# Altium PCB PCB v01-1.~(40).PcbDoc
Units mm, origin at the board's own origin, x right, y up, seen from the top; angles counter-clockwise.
Board outline 65 x 71 mm, 2 copper layers (Top Layer, Bottom Layer); 80 components, 36 nets, 162 pads, 11 vias.
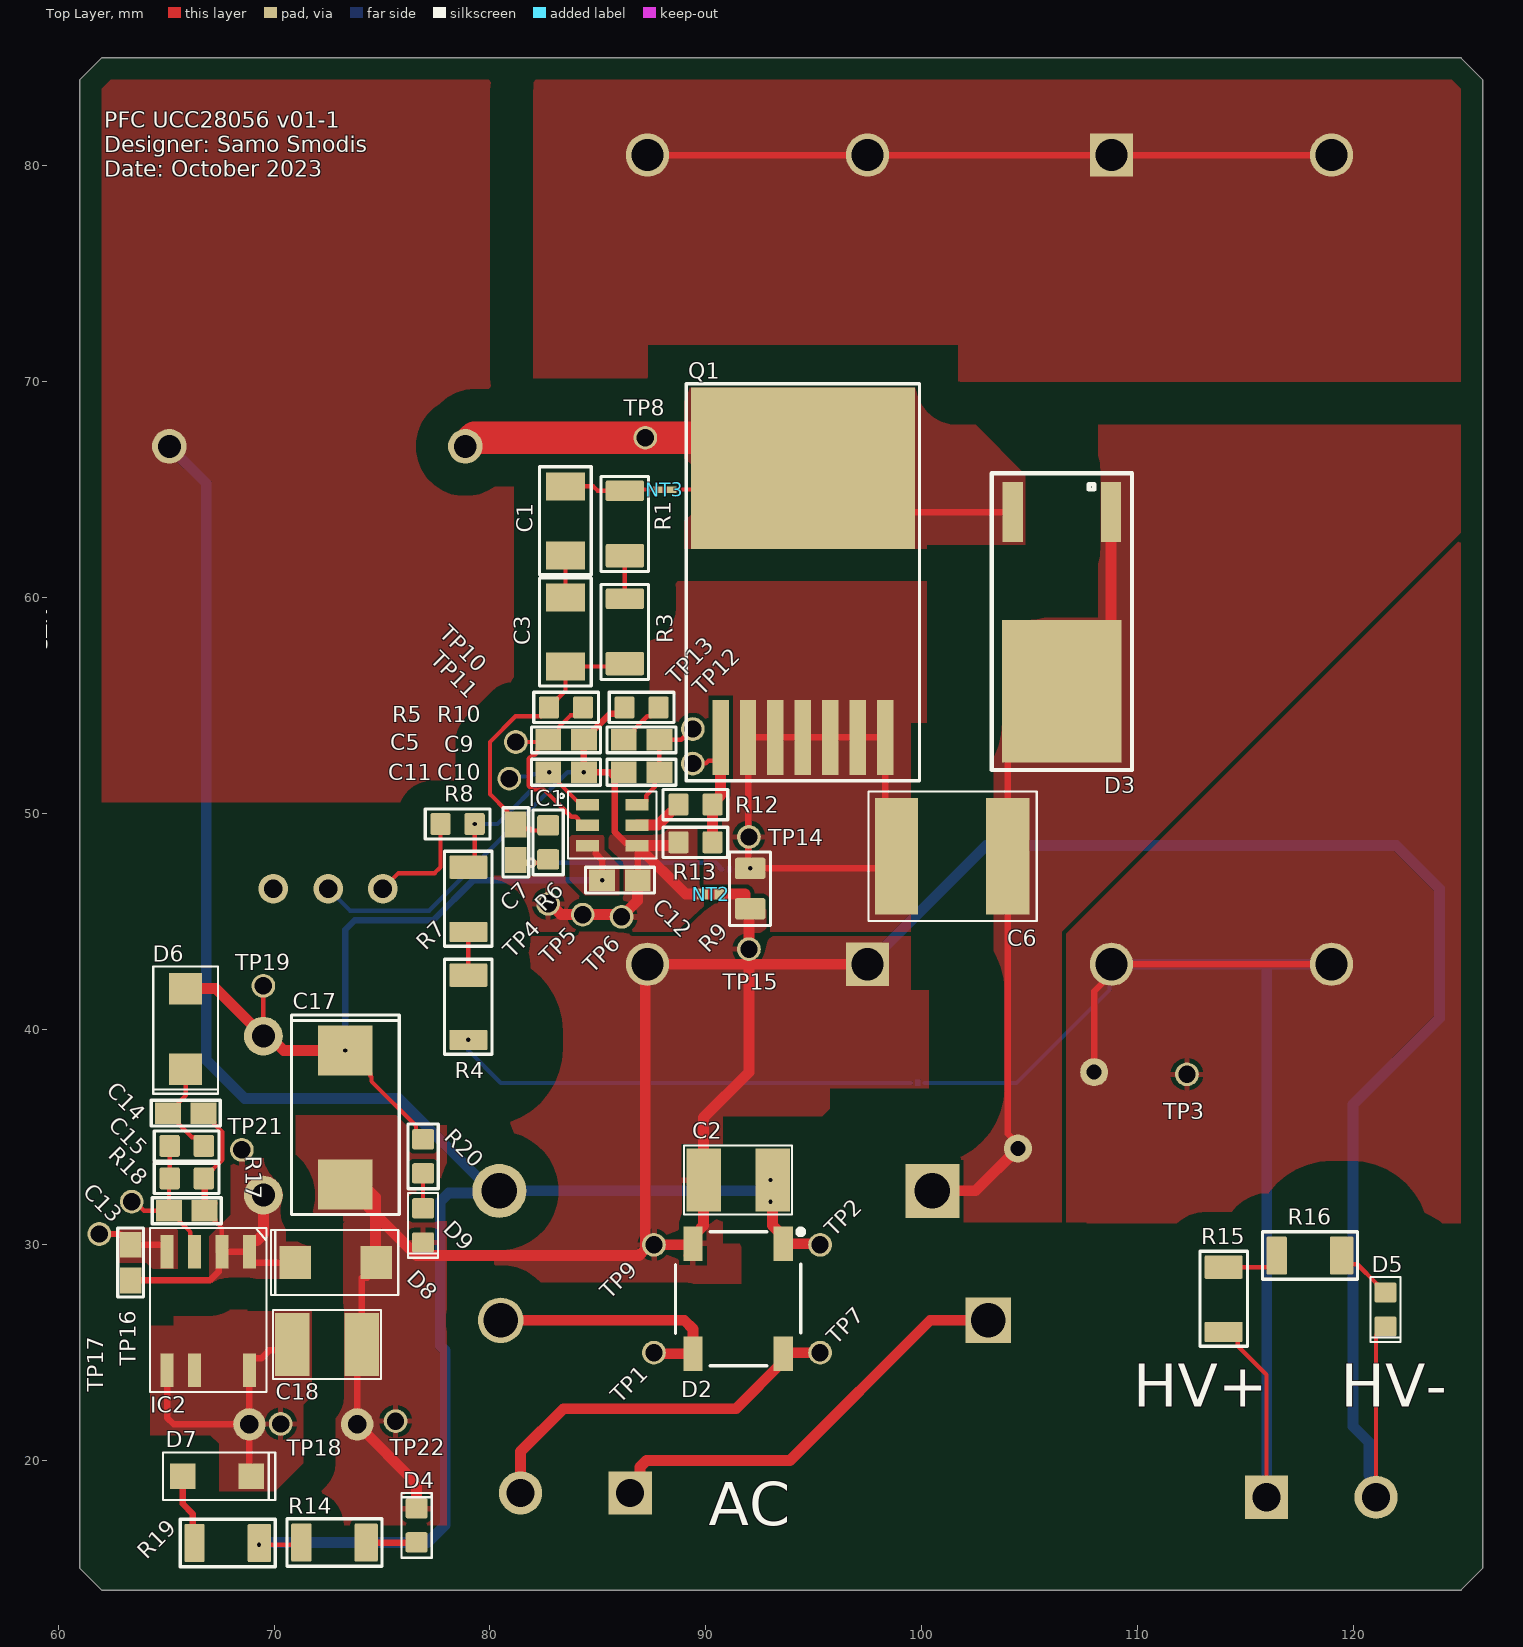
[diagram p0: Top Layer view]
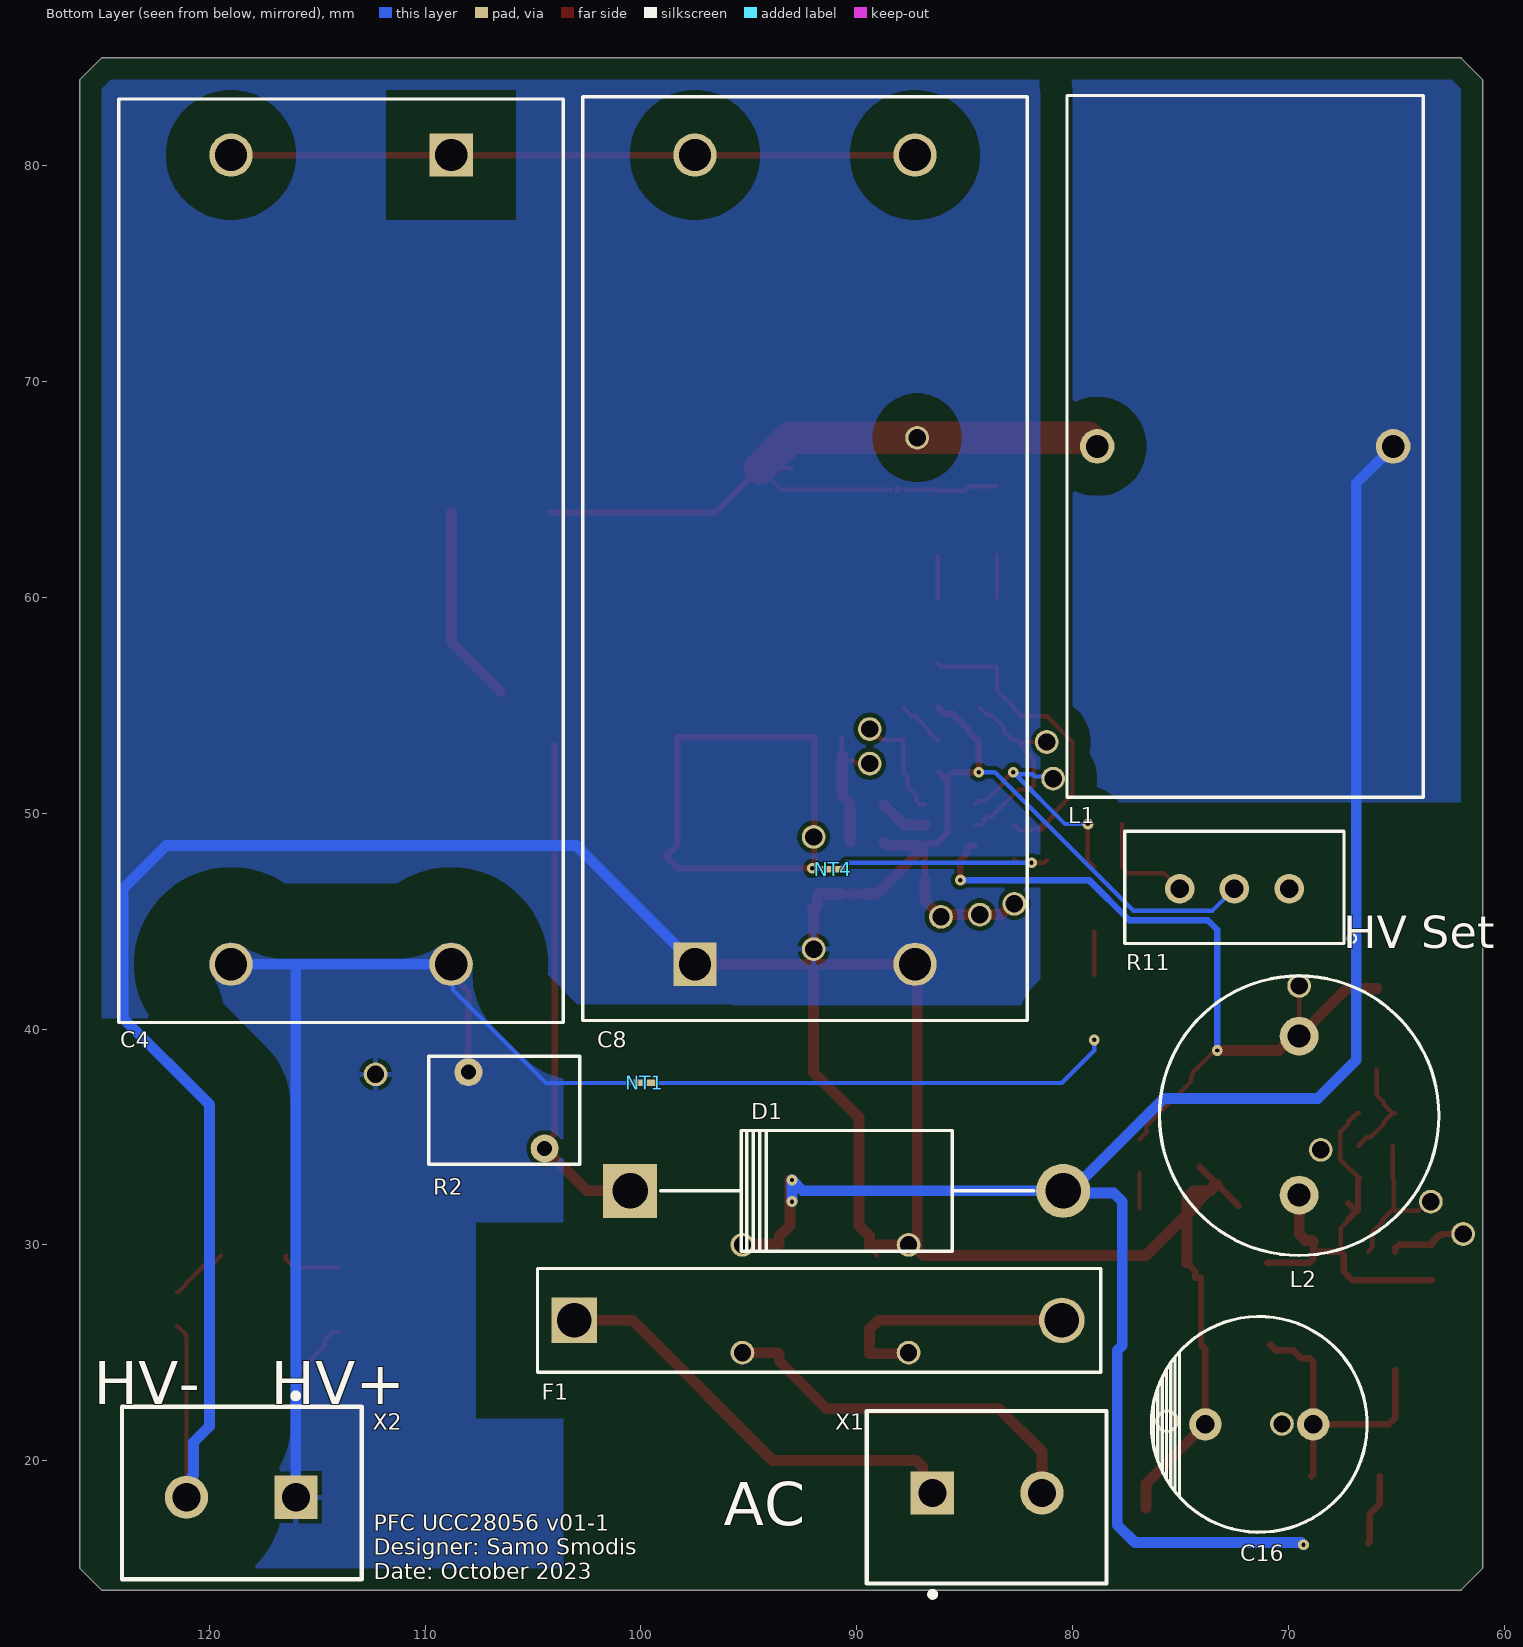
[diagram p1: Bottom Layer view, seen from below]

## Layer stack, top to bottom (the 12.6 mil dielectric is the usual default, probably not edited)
Top Solder: solder mask 0.0102, Solder Resist, Dk 3.5
Top Layer: signal copper 0.0356
Dielectric 1: dielectric 0.32, FR-4, Dk 4.8
Bottom Layer: signal copper 0.0356
Bottom Solder: solder mask 0.0102, Solder Resist, Dk 3.5

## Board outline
61,15 62,14 125,14 126,15 126,84 125,85 62,85 61,84

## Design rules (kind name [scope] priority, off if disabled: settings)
BoardOutlineClearance [All] p1: gap=1 ignorepadtopadclearanceinfootprint=FALSE
Clearance "1000V vs other" [InNetClass('1000V') vs Not InNetClass('1000V') AND Not InNetClass('500V')] p1: gap=3.5 ignorepadtopadclearanceinfootprint=TRUE
Clearance "500V vs other" [InNetClass('500V') vs Not InNetClass('500V')] p2: gap=2 ignorepadtopadclearanceinfootprint=TRUE
Clearance "375Vac vs other" [InNetClass('375Vac') vs Not InNetClass('375Vac')] p3: gap=1.5 ignorepadtopadclearanceinfootprint=FALSE
Clearance "375V vs other" [InNetClass('375V') vs Not InNetClass('375V')] p4: gap=1.5 ignorepadtopadclearanceinfootprint=FALSE
Clearance "AC vs ALL" [InNetClass('AC')] p5: gap=1.5 ignorepadtopadclearanceinfootprint=FALSE
Clearance Minimal [All] p6: gap=0.2 ignorepadtopadclearanceinfootprint=FALSE
Height [All] p1: minheight=0 maxheight=100 prefheight=12.7
HoleSize [All] p1: absolutevalues=TRUE maxlimit=10 minlimit=0.2 maxpercent=80.000 minpercent=20.000
MinimumSolderMaskSliver [All] p1: minsoldermaskwidth=0.2
PolygonConnect [All] p1: thpad.connectstyle=Relief thpad.reliefconductorwidth=0.254 thpad.reliefentries=4 thpad.polygonreliefangle="90 Angle" thpad.airgapwidth=0.2 smdpad.connectstyle=Relief smdpad.reliefconductorwidth=0.254 smdpad.reliefentries=4 smdpad.polygonreliefangle="90 Angle" smdpad.airgapwidth=0.2 via.connectstyle=Direct via.reliefconductorwidth=0.254 via.reliefentries=4 via.polygonreliefangle="90 Angle" via.airgapwidth=0.254
RoutingVias [All] p1: holewidth=0.2 width=0.5 viastyle="Through Hole" minholewidth=0.2 minwidth=0.5 maxholewidth=10 maxwidth=10
SolderMaskExpansion [All] p1: expansion=0.102 istentingtop=FALSE
Width [All] p1: maxlimit=20 minlimit=0.2 preferedwidth=0.3
27 further rules are at their usual default settings.

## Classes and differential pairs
net class 500V: NetC4_1 NetR4_1 NetR15_1
net class 1000V: NetC6_2 NetNT1_2 Udc
net class AC: L L_fuse N
net class 375V: HVIN NetD7_A ""
net class 375Vac: DRAIN FB NetC1_1 NetC1_2 NetC14_2 NetR1_1 SW VDD

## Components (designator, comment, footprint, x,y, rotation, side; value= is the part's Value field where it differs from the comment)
C1 "Generic Capacitor model" CAP_1206 83.5,63.55 r90 top
C2 "Generic Capacitor model" CAP_1210 91.5,33 r0 top
C3 "Generic Capacitor model" CAP_1206 83.5,58.4 r90 top
C4 "Generic Capacitor model" C4AQCBW5200A3FJ 108.8,80.5 r270 bottom
C5 "Generic Capacitor model" "CAP 0603" 83.525,53.4 r180 top
C6 "Generic Capacitor model" CAP_2220 98.84,48 r0 top
C7 "Generic Capacitor model" "CAP 0603" 81.2,48.65 r90 top
C8 "Generic Capacitor model" C4AQCBW5200A3FJ 97.5,43 r90 bottom
C9 "Generic Capacitor model" "CAP 0603" 87.025,53.4 r0 top
C10 "Generic Capacitor model" "CAP 0603" 87.025,51.9 r0 top
C11 "Generic Capacitor model" "CAP 0603" 83.525,51.9 r180 top
C12 "Generic Capacitor model" "CAP 0603" 86.025,46.9 r180 top
C13 "Generic Capacitor model" "CAP 0603" 65.949,31.579 r180 top
C14 "Generic Capacitor model" "CAP 0603" 65.9,36.1 r180 top
C15 "Generic Capacitor model" "CAP 0603" 63.349,29.179 r90 top
C16 "Cap_Polarized" "ELKO 10X20MM" 71.349,21.679 r0 bottom
C17 "Cap_Tantal" CAP_TANTAL_2917 73.3,35.9 r270 top
C18 "Generic Capacitor model" CAP_1210 72.449,25.379 r180 top
D1 "Diode" DO-201AD 100.5,32.5 r180 bottom
D2 "CD-MBL206SL" CD-MBL206SL 91.5,27.5 r270 top
D3 "Diode Schottky" TO252-2_DPAK_B 106.5,57.5 r180 top
D4 "Diode LED Red" DIODE_0603 76.6,17 r270 top
D5 "Diode LED Red" DIODE_0603 121.5,27 r90 top
D6 "Diode Schottky" SMAF 65.9,40 r90 top
D7 "Diode" SOD-123FL 67.349,19.279 r180 top
D8 "Diode Schottky" SMAF 72.849,29.179 r0 top
D9 "Diode LED Blue" DIODE_0603 76.9,30.9 r90 top
F1 "64600001003" 64600001003 103.1,26.5 r180 bottom
IC1 "UCC28056A" SOT-23-6 84.525,50.4 r0 top
IC2 "UCC28881" SOIC-7 68.849,29.679 r270 top
L1 "HCTI-680-3.4" HCTI-680-3.4 72,67 r0 bottom
L2 "AIUR-06-681K" AIUR-06-681K 69.5,32.3 r90 bottom
NT1 "NT" NETTIE_0.3MM 99.825,37.5 r180 bottom net-tie
NT2 "NT" NETTIE_0.5MM 90.25,46.25 r180 top net-tie
NT3 "NT" NETTIE_0.3MM 88.1,65 r0 top net-tie
NT4 "NT" NETTIE_0.3MM 91.1,47.4 r0 bottom net-tie
Q1 "Nmos_KS" "TO-263-7 D2PAK" 94.5,63.1 r0 top
R1 "Generic resistor model" RES_1206 86.25,63.4 r90 top
R2 "NTC 10R 1A" ICL101D05MIB 104.464,34.464 r45 bottom
R3 "Generic resistor model" RES_1206 86.25,58.4 r90 top
R4 "Generic resistor model" RES_1206 79,41.035 r270 top
R5 "Generic resistor model" RES_0603 83.525,54.9 r0 top
R6 "Generic resistor model" RES_0603 82.7,48.65 r90 top
R7 "Generic resistor model" RES_1206 79,46.04 r270 top
R8 "Generic resistor model" RES_0603 78.5,49.5 r0 top
R9 "Generic resistor model" Res_0805 92,46.5 r90 top
R10 "Generic resistor model" RES_0603 87.025,54.9 r0 top
R11 "67WR25KLF" RES-67WR10KLF 69.96,46.5 r0 bottom
R12 "Generic resistor model" RES_0603 89.525,50.4 r0 top
R13 "Generic resistor model" RES_0603 89.525,48.65 r0 top
R14 "Generic resistor model" RES_1206 72.8,16.2 r180 top
R15 "Generic resistor model" RES_1206 114,27.5 r270 top
R16 "Generic resistor model" RES_1206 118,29.5 r180 top
R17 "Generic resistor model" RES_0603 65.949,34.579 r0 top
R18 "Generic resistor model" RES_0603 65.949,33.079 r180 top
R19 "Generic resistor model" RES_1206 67.849,16.179 r180 top
R20 "Generic resistor model" RES_0603 76.9,34.1 r90 top
TP1 "Test Point" TEST_POINT_THT 87.6,25 r90 top
TP2 "Test Point" TEST_POINT_THT 95.3,30 r90 top
TP3 "Test Point" TEST_POINT_THT 112.3,37.9 r90 top
TP4 "Test Point" TEST_POINT_THT 82.7,45.8 r90 top
TP5 "Test Point" TEST_POINT_THT 84.3,45.3 r90 top
TP6 "Test Point" TEST_POINT_THT 86.1,45.2 r90 top
TP7 "Test Point" TEST_POINT_THT 95.3,25 r90 top
TP8 "Test Point" TEST_POINT_THT 87.2,67.4 r90 top
TP9 "Test Point" TEST_POINT_THT 87.6,30 r90 top
TP10 "Test Point" TEST_POINT_THT 81.2,53.3 r90 top
TP11 "Test Point" TEST_POINT_THT 80.9,51.6 r90 top
TP12 "Test Point" TEST_POINT_THT 89.4,52.3 r90 top
TP13 "Test Point" TEST_POINT_THT 89.4,53.9 r90 top
TP14 "Test Point" TEST_POINT_THT 92,48.9 r90 top
TP15 "Test Point" TEST_POINT_THT 92,43.7 r90 top
TP16 "Test Point" TEST_POINT_THT 63.4,32 r90 top
TP17 "Test Point" TEST_POINT_THT 61.9,30.5 r90 top
TP18 "Test Point" TEST_POINT_THT 70.3,21.7 r90 top
TP19 "Test Point" TEST_POINT_THT 69.5,42 r90 top
TP21 "Test Point" TEST_POINT_THT 68.5,34.4 r90 top
TP22 "Test Point" TEST_POINT_THT 75.627,21.827 r90 top
X1 "Screw Terminal 2pos" "Screw terminal 2pos 5.08mm" 83.985,18.3 r180 bottom
X2 "Screw Terminal 2pos" "Screw terminal 2pos 5.08mm" 118.5,18.5 r0 bottom

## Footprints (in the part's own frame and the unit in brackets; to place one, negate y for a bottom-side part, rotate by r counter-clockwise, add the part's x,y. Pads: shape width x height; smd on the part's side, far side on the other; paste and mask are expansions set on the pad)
64600001003 [mil] "Fuse holder 5x20mm"
  rect 83x83 / inner round 60 / far side rect 83x83 hole 63 paste-41.5 mask+0: 1(0,0)
  round 83 / inner round 60 / far side round 83 hole 63 paste-41.5 mask+0: 2(889.76,0)
  silkscreen extent -67,-94 961,94, body extent -62,-89 954,89, height 392
AIUR-06-681K [mm] "Power Inductor THT"
  round 1.8 hole 1.067 paste-0.787 mask+0: 1(0,0) 2(7.366,0)
  silkscreen extent -2.79,-6.48 10.16,6.48, body extent -2.68,-6.35 10.03,6.35, height 18.05
C4AQCBW5200A3FJ [mil] "Film Capacitor"
  round 79 hole 59 paste-39.5 mask+0: 1(0,-401.57) 2(1476.38,0) 2(1476.38,-401.58)
  rect 79x79 hole 59 paste-39.5 mask+0: 1(0,0)
  silkscreen extent -102,-606 1583,205, body extent -98,-602 1579,201, height 1583
"CAP 0603" [mm] "CAP 0603"
  rect 1.2x1 smd paste+0 mask+0: 1(-0.825,0) 2(0.825,0)
  silkscreen extent -1.6,-0.6 1.6,0.6, body extent -0.87,-0.48 0.87,0.48, height 0.87
CAP_1206 [mm]
  rect 1.3x1.8 smd: 1(-1.6,0) 2(1.6,0)
  silkscreen extent -2.5,-1.2 2.5,1.2, body extent -1.7,-0.9 1.7,0.9, height 1.81
CAP_1210 [mm] "Cap SMD 1210"
  rect 1.6x2.904 smd paste+0 mask+0: 1(-1.6,0) 2(1.6,0)
  silkscreen extent -2.5,-1.6 2.5,1.6, body extent -2.85,-1.95 2.85,1.95, height 0.25
CAP_2220 [mm] "CAP_2220"
  rect 2.01x5.4 smd: 1(0,0) 2(5.16,0)
  silkscreen extent -1.3,-3 6.5,3
CAP_TANTAL_2917 [mm] "CAP TANTAL 2917"
  rect 2.31x2.52 smd: +(-3.1,0) -(3.1,0)
  silkscreen extent -4.75,-2.5 4.5,2.5, body extent -3.65,-2.15 3.65,2.15, height 3.11
CD-MBL206SL [mil] "Rectifier bridge"
  rect 62.75x35.03 smd paste+0 mask+0: +(-100.37,82.5) -(-100.37,-82.5) AC1(100.37,82.5) AC2(100.37,-82.5)
  silkscreen extent -126,-114 122,118, body extent -116,-106 116,106, height 46
DIODE_0603 [mm] "RES 0603"
  rrect20% 0.94x1.02 smd: A(0.79,0) K(-0.79,0)
  silkscreen extent -1.5,-0.7 1.5,0.7, body extent -0.8,-0.4 0.8,0.4, height 0.46
DO-201AD [mm] "Diode THT Vishay"
  round 2.5 hole 1.651 paste-1.079 mask+0: A(20.066,0)
  rect 2.5x2.5 hole 1.651 paste-1.079 mask+0: K(0,0)
  silkscreen extent 1.4,-2.8 18.7,2.8, body extent -0.7,-2.67 20.76,2.67, height 5.34
"ELKO 10X20MM" [mm] "ELKO THT 10x20mm 5mm Pitch"
  round 1.5 hole 0.85: +(-2.5,0) -(2.5,0)
  silkscreen extent -5,-5 5,5, body extent -5,-5 5,5, height 20
HCTI-680-3.4 [mm] "Toroidal Inductor"
  round 1.6 hole 1.06: 1(-6.858,0) 2(6.858,0)
  silkscreen extent -8.25,-16.26 8.25,16.26, body extent -8.25,-16.21 8.26,16.21, height 34.27
ICL101D05MIB [mm] "NTC THT 5mm Disk"
  round 1.3 hole 0.7: 1(0,0) 2(5,0)
  silkscreen extent -1.67,-4.17 6.82,4.32
NETTIE_0.3MM [mm] "NetTie 0.3mm"
  rect 0.45x0.3 smd paste-5 mask+0.102: 1(-0.325,0) 2(0.325,0)
  Top Layer region: -0.125,0.15 0.125,0.15 0.125,-0.15 -0.125,-0.15
NETTIE_0.5MM [mm] "NetTie 0.5mm"
  rect 0.5x0.5 smd paste-5 mask+0.102: 1(-0.4,0) 2(0.4,0)
  Top Layer region: -0.175,-0.25 0.175,-0.25 0.175,0.25 -0.175,0.25
RES-67WR10KLF [mil] "Trimm Pot 10k"
  round 54 / inner round 60 / far side round 54 hole 34 paste-27 mask+0: 1(0,0) 2(100,0) 3(200,0)
  silkscreen extent -122,-105 300,100
RES_0603 [mm] "RES 0603"
  rrect20% 0.94x1.02 smd: 1(-0.79,0) 2(0.79,0)
  silkscreen extent -1.5,-0.7 1.5,0.7, body extent -0.8,-0.4 0.8,0.4, height 0.46
Res_0805 [mm]
  rrect25% 1x1.42 smd: 1(-0.925,-0.057) 2(0.945,-0.057)
  silkscreen extent -1.7,-1 1.7,0.9, body extent -1,-0.62 1,0.62, height 0.61
RES_1206 [mm]
  rrect14% 1.09x1.77 smd: 1(-1.465,0)
  rrect14% 0.94x1.77 smd: 2(1.54,0)
  silkscreen extent -2.2,-1.1 2.2,1.1, body extent -1.55,-0.78 1.55,0.77, height 0.56
"Screw terminal 2pos 5.08mm" [mm] "Screw terminal 2pos 5.08mm"
  rect 2x2 hole 1.3 paste-1000 mask+0: 1(-2.515,0.2)
  round 2 hole 1.3 paste-1000 mask+0: 2(2.565,0.2)
  silkscreen extent -5.56,-4.62 5.56,4, body extent -5.05,-3.93 5.11,4.07, height 10.02
SMAF [mm] "DIODE SMAF"
  rect 1.46x1.53 smd: A(1.875,0) K(-1.875,0)
  silkscreen extent -3,-1.5 2.9,1.5, body extent -2.3,-1.3 2.3,1.3, height 1.11
SOD-123FL [mm]
  rect 1.18x1.17 smd: A(1.59,0) K(-1.59,0)
  silkscreen extent -2.7,-1.1 2.5,1.1, body extent -1.85,-0.95 1.85,0.95, height 1.35
SOIC-7 [mm] "SOIC-7"
  rect 1.55x0.6 smd: 1(0,0) 2(0,-1.27) 3(0,-2.54) 4(0,-3.81) 5(5.5,-3.81) 6(5.5,-2.54) 8(5.5,0)
  silkscreen extent -1.1,-4.6 6.5,0.8, body extent -0.2,-4.4 5.8,0.6, height 1.75
SOT-23-6 [mm]
  rect 1.072x0.532 smd: 1(0,0) 2(0,-0.95) 3(0,-1.9) 4(2.298,-1.9) 5(2.298,-0.95) 6(2.298,0)
  silkscreen extent -1.3,-2.5 3.2,0.6, body extent -0.3,-2.35 2.5,0.55, height 1.2
TEST_POINT_THT [mm] "Test point hole"
  round 1.1 hole 0.8: 1(0,0)
TO252-2_DPAK_B [mil] "Check internal diode connection pins!"
  rect 36.97x109.37 smd paste+0 mask+0: A(89.57,-253.97) K(-89.57,-253.97)
  rect 218x260 smd paste+0 mask+0: K(0,73)
  silkscreen extent -128,-325 128,217, body extent -132,-287 132,172, height 94
"TO-263-7 D2PAK" [mil] "SMD Mosfet"
  rect 409x294 smd paste+0 mask+0: D(0,113.5)
  rect 29.97x137.37 smd paste+0 mask+0: G(-150,-377.47) KS(-100,-377.47) S(-50,-377.47) S(0,-377.47) S(50,-377.47) S(100,-377.47) S(150,-377.47)
  silkscreen extent -213,-457 213,268, body extent -202,-424 202,241, height 180

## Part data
C1 C3: library part Cap, Capacitance=22p, Case Code (Imperial)=1206, Manufacturer=Walsin, Manufacturer Part Number=1206N220J102CT, Supplier Part Number 1=791-1206N220J102CT, Voltage Rating=1kV
C2 C18: library part Cap, Capacitance=100n, Case Code (Imperial)=1210, Manufacturer=Kemet, Manufacturer Part Number=C1210C104KBRACAUTO, Supplier Part Number 1=80-C1210C104KBRAUTO, Voltage Rating=630V
C4 C8: library part Cap, Capacitance=20u, Manufacturer=Kemet, Manufacturer Part Number=C4AQCBW5200A3FJ, Supplier Part Number 1=80-C4AQCBW5200A3FJ, Voltage Rating=650V
C5: library part Cap, Capacitance=10p, Case Code (Imperial)=0603, Manufacturer=Kemet, Manufacturer Part Number=C0603C100J1GAC, Supplier Part Number 1=80-C0603C100J1GAC, Voltage Rating=100V
C6: library part Cap, Capacitance=22n, Case Code (Imperial)=2220, Voltage Rating=2000V
C7: library part Cap, Capacitance=3n9, Case Code (Imperial)=0603, Manufacturer=Vishay, Manufacturer Part Number=VJ0603Y392KXACW1BC, Supplier Part Number 1=77-VJ0603Y392KXACBC, Voltage Rating=50V
C9 C14: library part Cap, Capacitance=180n, Case Code (Imperial)=0603, Manufacturer=Murata, Manufacturer Part Number=GCJ188R91H184KA01D, Supplier Part Number 1=81-GCJ188R91H184KA1D, Voltage Rating=50V
C10: library part Cap, Capacitance=82n, Case Code (Imperial)=0603, Manufacturer=Murata, Manufacturer Part Number=GCM188L81H823KA57D, Supplier Part Number 1=81-GCM188L81H823KA7D, Voltage Rating=50V
C11 C13: library part Cap, Capacitance=3n, Case Code (Imperial)=0603, Manufacturer=Murata, Manufacturer Part Number=GRM1885C1H302JA01D, Supplier Part Number 1=81-GRM1885C1H302JA1D, Voltage Rating=50V
C12 C15: library part Cap, Capacitance=3u3, Case Code (Imperial)=0603, Manufacturer=TDK, Manufacturer Part Number=C1608X5R1V335M080AC, Supplier Part Number 1=810-C1608X5R1V335M0C, Voltage Rating=35V
C16: "Generic polarized cap symbol", Capacitance=10u, Manufacturer=Panasonic, Manufacturer Part Number=EEU-EE2W100U, Supplier Part Number 1=667-EEU-EE2W100U, Voltage Rating=450V
C17: "Generic tantal cap symbol", Capacitance=100u, Manufacturer=Kemet, Manufacturer Part Number=T491X107M025AT, Supplier Part Number 1=80-T491X107M025, Voltage Rating=25V
D1: "General Diode symbol", Forward Current=3A, Manufacturer=Vishay, Manufacturer Part Number=BY255P-E3/73, Reverse Voltage=1300V, Supplier Part Number 1=625-BY255P-E3/73
D2: "Diode Bridge 600V 2A", Manufacturer=Bourns
D3: "General Schottky Diode symbol", Forward Current=2A, Manufacturer=Infineon, Manufacturer Part Number=IDM02G120C5XTMA1, Reverse Voltage=1200V, Supplier Part Number 1=726-IDM02G120C5XTMA1
D4 D5: "Generic red LED symbol"
D6 D8: "General Schottky Diode symbol", Forward Current=2A, Manufacturer=Comchip, Manufacturer Part Number=AES2JF-HF, Reverse Voltage=600V, Supplier Part Number 1=750-AES2JF-HF
D7: "General Diode symbol", Forward Current=1A, Manufacturer=MCC, Manufacturer Part Number=GS1Z-LTP, Reverse Voltage=2kV, Supplier Part Number 1=833-GS1Z-LTP
D9: "Generic blue LED symbol"
F1: "Fuse Holder 5X20MM 250V 6.3A", Manufacturer=Littlefuse, Supplier Part Number 1=576-64600001003
IC1: "PFC TM IC", Manufacturer="Texas Instruments"
IC2: "700-V Lowest Quiescent current off-line switcher", Manufacturer="Texas Instruments", Supplier Part Number 1=UCC28881D
L1: "Inductor THT 680uH 3.4A 150mR", Inductance=680u, Manufacturer="Bel Signal Transformer", Resistance=150mR, Saturation current=3.4Asat, Supplier Part Number 1=530-HCTI-680-3.4
L2: "Power Inductor THT 680uH 820mA 740mR", Inductance=680uH, Manufacturer=Abracon, Resistance=740mR, Saturation current=820mA, Supplier Part Number 1=815-AIUR-06-681K
NT1 NT2 NT3 NT4: library part NetTie, "Net Tie"
Q1: "Generic Nmos symbol with Kelvin Source", Manufacturer=GeneSiC, Manufacturer Part Number=G3R350MT12J, Supplier Part Number 1=905-G3R350MT12J, Voltage=1200V
R1 R3: library part Res, Case Code (Imperial)=1206, Manufacturer=ROHM, Manufacturer Part Number=KTR18EZPF4994, Resistance=4M99, Resistance Tolerance=1%, Supplier Part Number 1=755-KTR18EZPF4994
R2: library part ICL101D05MIB, "NTC 10R 1A 5mm THT", Manufacturer=Eaton, Resistance=10R, Supplier Part Number 1=504-ICL101D05MIB
R4 R7: library part Res, Case Code (Imperial)=1206, Manufacturer=ROHM, Manufacturer Part Number=KTR18EZPF5104, Resistance=5M1, Resistance Tolerance=1%, Supplier Part Number 1=755-KTR18EZPF5104
R5: library part Res, Case Code (Imperial)=0603, Manufacturer=Yageo, Manufacturer Part Number=AC0603JR-073KL, Resistance=3k, Supplier Part Number 1=603-AC0603JR-073KL
R6: library part Res, Case Code (Imperial)=0603, Manufacturer=Vishay, Manufacturer Part Number=CRCW060324K3FKEB, Resistance=24k3, Resistance Tolerance=1%, Supplier Part Number 1=71-CRCW060324K3FKEB
R8: library part Res, Case Code (Imperial)=0603, Manufacturer=Yageo, Manufacturer Part Number=RT0603DRE0725K5L, Resistance=25k5, Resistance Tolerance=1%, Supplier Part Number 1=603-RT0603DRE0725K5L
R9: library part Res, Case Code (Imperial)=0805, Manufacturer=Eaton, Manufacturer Part Number=MFLA0805R2000FA, Power Rating=250mW, Resistance=200mR, Supplier Part Number 1=504-MFLA0805R2000FA
R10: library part Res, Case Code (Imperial)=0603, Manufacturer=Panasonic, Manufacturer Part Number=ERJ-3EKF1653V, Resistance=165k, Resistance Tolerance=1%, Supplier Part Number 1=667-ERJ-3EKF1653V
R11: "Trimpot, 25 kohm, Through Hole, 20 Turns, Multi Turn, Cermet, Top Adjust,", Manufacturer="BI Technologies", Resistance=25k, Supplier Part Number 1=858-67WR25KLF
R12: library part Res, Case Code (Imperial)=0603, Power Rating=?mW, Resistance=10R, Resistance Tolerance=?%, Supplier Part Number 1=?
R13: library part Res, Case Code (Imperial)=0603, Power Rating=?mW, Resistance=82k, Resistance Tolerance=?%, Supplier Part Number 1=?
R14: library part Res, Case Code (Imperial)=1206, Manufacturer=KOA, Manufacturer Part Number=RN73H2BTTD3523F100, Power Rating=?mW, Resistance=352k, Resistance Tolerance=?%, Supplier Part Number 1=660-RN73H2BT3523F100
R15 R16: library part Res, Case Code (Imperial)=1206, Manufacturer=Yageo, Manufacturer Part Number=RT1206FRE07510KL, Power Rating=?mW, Resistance=510k, Resistance Tolerance=?%, Supplier Part Number 1=603-RT1206FRE07510KL
R17: library part Res, Case Code (Imperial)=0603, Manufacturer=Yageo, Manufacturer Part Number=RT0603BRD07135KL, Power Rating=?mW, Resistance=135k, Resistance Tolerance=1%, Supplier Part Number 1=603-RT0603BRD07135KL
R18: library part Res, Case Code (Imperial)=0603, Manufacturer=TE, Manufacturer Part Number=CRG0603F10K/10, Power Rating=?mW, Resistance=10k, Resistance Tolerance=1%, Supplier Part Number 1=279-CRG0603F10K/10
R19: library part Res, Case Code (Imperial)=1206, Manufacturer=Koa, Manufacturer Part Number=SG73P2BTTD100J, Power Rating=750mW, Resistance=10R, Supplier Part Number 1=660-SG73P2BTTD100J
R20: library part Res, Case Code (Imperial)=0603, Manufacturer=Kamaya, Manufacturer Part Number=RMC1/16K1502FTP, Resistance=15k, Supplier Part Number 1=791-RMC1/16K1502FTP
TP1 TP2 TP3 TP4 TP5 TP6 TP7 TP8 TP9 TP10 TP11 TP12 TP13 TP14 TP15 TP16 TP17 TP18 TP19 TP21 TP22: "Test point"
X1 X2: "Screw terminal 2 pos, pith 5.08mm", Color=Black, Current=15A, Current Rating=16A, Flammability Rating="UL94 V-0", Manufacturer=Weidmuller, Manufacturer Part Number=1760510000, Max Operating Temperature=120°C, Max Supply Voltage=300V, Min Operating Temperature=-50°C, Package Quantity=500, Supplier Part Number 1=4477091

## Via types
v1: diameter 0.5, hole 0.2, Top Layer to Bottom Layer, tented both sides, 11 vias

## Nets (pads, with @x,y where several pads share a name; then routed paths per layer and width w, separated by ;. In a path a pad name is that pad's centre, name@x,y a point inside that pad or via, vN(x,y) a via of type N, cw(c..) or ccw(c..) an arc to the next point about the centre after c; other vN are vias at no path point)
15V: C12.2 C17.+ D6.A IC1.3 L2.2 R20.2 TP19.1 | length 37.1
  Top Layer w0.2: L2.2 TP19.1 ; v1(73.3,39) 73.405,39 74.46,37.945 74.46,37.84 74.515,37.785 74.515,37.572 76.574,35.513 76.574,35.216 R20.2
  Top Layer w0.3: IC1.3 84.795,48.5 84.911,48.384 84.911,48.114 85.2,47.825 v1(85.2,46.9)
  Top Layer w0.5: D6.A 67.291,41.875 L2.2 69.777,39.666 70.443,39 v1(73.3,39)
  Bottom Layer w0.3: v1(73.3,39) 73.3,44.6 73.736,45.036 77.372,45.036 79.236,46.9 v1(85.2,46.9)
COMP: C9.2 C10.2 IC1.6 TP13.1 | length 5.3
  Top Layer w0.2: IC1.6 87.07,50.4 87.236,50.566 87.236,50.813 87.64,51.217 87.64,51.69 C10.2 C9.2 88.864,53.4 89.364,53.9 TP13.1
DRAIN: D3.A L1.2 NT3.2 Q1.D TP8.1 | length 34.9
  Top Layer w0.2: NT3.2 93.517,65 Q1.D Q1.D@93.039,65.983
  Top Layer w0.3: Q1.D 96.532,63.951 D3.A
  Top Layer w1.5: L1.2 78.885,67 79.285,67.4 93.083,67.4 Q1.D
DRV: IC1.5 R12.1 | length 2.3
  Top Layer w0.5: IC1.5 87.785,49.45 88.475,50.14 88.515,50.14 88.735,50.36 R12.1
FB: C13.2 IC2.3 R17.1 R18.2 TP16.1 | length 8
  Top Layer w0.2: TP16.1 63.546,32 63.967,31.579 C13.2 ; R17.1 R18.2 65.124,33.044 C13.2 ; IC2.3 66.116,29.871 66.116,30.586 65.624,31.079 C13.2@65.624,31.179 ; C13.2 C13.2@65.224,31.579 ; C13.2 C13.2@65.224,31.579 ; C13.2@65.224,31.579 C13.2@65.624,31.179 ; C13.2@65.224,31.579 C13.2@65.624,31.179
GND: C5.1 C10.1 C11.1 C12.1 IC1.4 NT2.2 R10.1 R11.2 R13.1 TP4.1 TP5.1 TP6.1 | length 37.6
  Top Layer w0.3: C10.1@85.775,51.65 85.525,51.9 v1(84.35,51.9) C5.1 84.45,53.4 84.8,53.75 84.8,53.85 85.562,54.612 85.947,54.612 R10.1 ; C10.1 85.862,51.563 85.787,51.563 85.775,51.55 85.775,49.136 86.295,48.616 86.707,48.616 IC1.4 ; C12.1 IC1.4@86.85,48.473
  Top Layer w0.5: TP4.1 82.793,45.8 83.293,45.3 TP5.1 86,45.3 TP6.1 86.843,45.943 86.843,46.893 C12.1 ; IC1.4@86.85,48.473 89.073,46.25 NT2.2 ; IC1.4@87.116,48.5 88.585,48.5 R13.1
  Bottom Layer w0.2: R11.2 73.514,45.486 77.186,45.486 83.6,51.9 v1(84.35,51.9)
HVIN: C16.+ C18.2 D7.K IC2.5 IC2.6 IC2.8 TP18.1 | length 13.8
  Top Layer w0.3: IC2.5 65.039,21.989 65.349,21.679 C16.+ ; D7.K 68.849,19.369 C16.+ ; C18.2 70.574,25.104 69.774,25.104 69.404,24.734 68.999,24.734 68.849,24.584 IC2.8 C16.+
L: F1.1 X1.1 | length 20.4
  Top Layer w0.5: X1.1 86.957,18.957 86.957,19.707 87.25,20 93.9,20 100.4,26.5 F1.1
L_fuse: D2.AC2 F1.2 TP1.1 | length 12
  Top Layer w0.5: F1.2 89,26.5 89.404,26.096 D2.AC2 87.649,24.951 TP1.1
N: D2.AC1 TP7.1 X1.2 | length 17.9
  Top Layer w0.5: X1.2 81.42,20.42 83.404,22.404 91.401,22.404 93.595,24.599 D2.AC1 93.645,25 TP7.1
NetC1_1: C1.1 C3.2 | length 2
  Top Layer w0.2: C3.2 C1.1
NetC1_2: C1.2 NT3.1 R1.2 | length 4.4
  Top Layer w0.2: C1.2 84.783,65.15 84.983,64.95 R1.2@86.24,64.95 ; R1.2 R1.2@86.24,64.95 ; NT3.1 86.29,65 R1.2@86.24,64.95
NetC3_1: C3.1 C7.2 R3.1 R5.1 R6.2 | length 15
  Top Layer w0.2: C7.2 81.475,49.2 C7.2@81.6,49.2 ; 81.883,49.2 81.967,49.2 ; R6.2 82.46,49.2 81.967,49.2 ; R3.1 86.115,56.8 C3.1 83.5,55.665 83.145,55.31 83.105,55.31 82.735,54.94 82.735,54.86 82.365,54.49 81.188,54.49 80,53.302 80,50.885 80.8,50.085 80.8,49.975 81.287,49.488 81.396,49.488 81.6,49.285 81.883,49.285 81.967,49.2
NetC4_1: C4.1 C8.2 | length 31.7
  Top Layer w0.3: C8.2@87.3,80.5 97.5,80.5 108.8,80.5 C4.1@119,80.5
NetC6_2: C6.2 D1.K D3.K R2.1 | length 32.9
  Top Layer w0.3: D3.K@104,53.146 C6.2 104,35.14 104.464,34.676 R2.1
  Top Layer w0.5: D1.K 102.5,32.5 R2.1 ; D3.K@106.5,55.646 108.775,57.921 D3.K@108.775,63.951
NetC7_1: C7.1 NT4.1 R6.1 | length 10.7
  Top Layer w0.2: C7.1 81.325,47.7 v1(81.9,47.7) 82.54,47.7 R6.1
  Bottom Layer w0.2: v1(81.9,47.7) 90.475,47.7 90.65,47.525 90.65,47.45 90.7,47.4 NT4.1
NetC9_1: C9.1 R10.2 | length 2.3
  Top Layer w0.2: C9.1 86.3,53.4 86.7,53.8 86.7,53.9 87.29,54.49 87.445,54.49 87.815,54.86 R10.2
NetC14_2: C14.2 D6.K R17.2 | length 4.7
  Top Layer w0.2: C14.2 C14.2@65.175,36.1 ; D6.K 65.9,36.925 65.575,36.6 65.575,36.5 C14.2@65.175,36.1 ; R17.2 66.739,34.612 66.369,34.982 66.193,34.982 65.575,35.6 65.575,35.7 C14.2@65.175,36.1
NetD4_A: D4.A R14.1 | length 2.3
  Top Layer w0.3: R14.1 76.59,16.2 D4.A
NetD5_A: D5.A R16.1 | length 2.8
  Top Layer w0.2: R16.1 119.868,29.097 120.193,29.097 121.09,28.2 121.09,28.16 121.46,27.79 D5.A
NetD7_A: D7.A R19.2 | length 3.3
  Top Layer w0.3: D7.A 65.759,17.994 66.239,17.514 66.239,16.249 R19.2
NetD9_A: D9.A R20.1 | length 1.6
  Top Layer w0.2: D9.A R20.1
NetNT1_2: NT1.2 R4.2 | length 21.8
  Bottom Layer w0.2: v1(79,39.495) 79,39 ; 79.1,38.9 79,39 ; NT1.2 80.5,37.5 79,39
NetQ1_G: Q1.G R12.2 R13.2 TP12.1 | length 6.5
  Top Layer w0.2: TP12.1 90,52.3 90.127,52.427 90.409,52.427 90.69,52.707 Q1.G
  Top Layer w0.5: R13.2 R12.2 90.315,50.44 90.69,50.815 Q1.G@90.69,52.707
NetR1_1: R1.1 R3.2 | length 2
  Top Layer w0.2: R3.2 R1.1
NetR4_1: R4.1 R7.2 | length 2
  Top Layer w0.2: R4.1 R7.2
NetR8_1: R8.1 R11.3 | length 5.1
  Top Layer w0.2: R11.3 75.763,47.223 77.437,47.223 77.71,47.496 R8.1
NetR15_1: R15.1 R16.2 | length 2.8
  Top Layer w0.2: R15.1 116.09,28.965 116.46,29.335 R16.2
PGND: C2.1 C8.1 C16.- C17.- C18.1 D2.- D4.K D5.K D8.A D9.K NT2.1 R9.1 TP9.1 TP15.1 TP22.1 X2.2 | length 148.3
  Top Layer w0.2: D2.-@89.06,29.5 89.404,29.845 89.404,29.947 D2.- ; X2.2 121.065,25.775 121.09,25.8 121.09,25.84 121.46,26.21 D5.K
  Top Layer w0.3: C17.-@72.3,31.8 C17.- C17.-@74.11,33.61 ; C16.- 73.849,25.179 C18.1 74.049,28.469 74.314,28.469 74.314,28.769 D8.A
  Top Layer w0.5: C16.- 76.6,18.927 D4.K ; D8.A 74.7,29.202 74.7,31.4 ; TP9.1 89.352,30 D2.-@89.404,29.947 ; D2.- 89.404,30.401 89.599,30.596 89.607,30.596 89.9,30.889 C2.1 89.9,35.9 92,38 92,43 ; NT2.1 91.824,46.25 R9.1@91.824,45.693 ; R9.1 92,45.517 TP15.1@92,43.176 ; C8.1@97.5,43 92,43 ; C17.-@73.705,32.5 74.407,32.5 74.7,32.207 74.7,31.4 ; C17.-@73.705,32.5 73.6,32.5 C17.- 73.405,32.8 C17.-@73.705,32.5 ; C17.-@73.705,32.5 74.31,31.895 74.31,31.79 74.7,31.4 ; 74.7,31.4 76.6,29.5 86.907,29.5 87.2,29.793 87.2,42.9 87.3,43 91.824,43 ; 91.824,43 92,43 ; 91.824,43 TP15.1@92,43.176 ; 92,43 TP15.1@92,43.176
  Bottom Layer w0.5: C8.1@97.5,43 103,48.5 122,48.5 124,46.5 124,40.5 120,36.5 120,21.588 120.735,20.853 120.735,19.343 120.778,19.3 120.778,18.587 X2.2
SOURCE: C6.1 NT4.2 Q1.KS Q1.S R9.2 TP14.1 | length 25.9
  Top Layer w0.3: R9.2@91.96,47.542 v1(92.057,47.445) 98.285,47.445 C6.1 98.31,48.53 98.31,53.512 97.04,53.512 95.77,53.512 94.5,53.512 93.23,53.512 Q1.KS R9.2@91.96,47.542
  Bottom Layer w0.2: NT4.2 91.437,47.412 92.025,47.412 v1(92.057,47.445)
SW: C13.1 C14.1 C15.1 D8.K IC2.1 IC2.2 L2.1 R18.1 TP21.1 | length 21
  Top Layer w0.2: C14.1 66.825,36.1 67.225,35.7 67.225,35.6 67.6,35.225 67.6,33.94 67.149,33.489 67.109,33.489 66.739,33.119 R18.1 ; C13.1 66.829,31.579 66.874,31.579 67.274,31.179 67.274,31.079 67.579,30.774 IC2.2
  Top Layer w0.3: C15.1 67.024,28.354 67.429,28.759 67.429,29.529 IC2.2 IC2.1 ; R18.1 66.774,33.044 C13.1 C13.1@66.829,31.579 ; C13.1@67.179,31.229 C13.1@66.829,31.579 ; C13.1@67.224,31.929 66.874,31.579 C13.1@66.829,31.579 ; IC2.1@68.999,30.234 68.968,30.204 68.849,30.084 IC2.1 ; D8.K 68.999,29.179 68.849,29.329 IC2.1
  Top Layer w0.5: IC2.1@68.849,30.084 68.849,30.154 68.899,30.204 68.968,30.204 69.207,30.204 69.5,30.497 L2.1
Udc: C4.2 NT1.1 R2.2 R15.2 TP3.1 X2.1 | length 70.7
  Top Layer w0.2: R15.2 114.283,25.96 114.653,25.59 114.653,25.307 115.985,23.975 X2.1
  Top Layer w0.3: R2.2 108,41.745 108.8,42.545 108.8,43 C4.2@119,43
  Bottom Layer w0.2: NT1.1 104.4,37.5 108.714,41.814 108.714,42.914 C4.2@108.8,43
  Bottom Layer w0.5: C4.2@108.8,43 116,43 ; X2.1 116,18.315 116,43 ; C4.2@119,43 116,43
VDD: C15.2 IC2.4 TP17.1 | length 3.6
  Top Layer w0.3: TP17.1 62.852,30.5 62.899,30.454 62.999,30.454 63.349,30.104 C15.2 64.889,30.004 65.039,29.854 IC2.4
VOSNS: C11.2 IC1.1 R7.1 R8.2 TP11.1 | length 11
  Top Layer w0.2: R7.1 79.29,47.795 v1(79.29,49.5) ; C11.2 v1(82.75,51.9) 82.8,51.9 83.2,51.5 83.2,51.4 84.034,50.566 84.359,50.566 IC1.1
  Bottom Layer w0.2: v1(79.29,49.5) 80.35,49.5 82.609,51.759 v1(82.75,51.9) 82.669,51.9 82.569,51.8 81.85,51.8 81.75,51.7 81,51.7 TP11.1
ZCD/CS: C5.2 IC1.2 R5.2 TP10.1 | length 9.8
  Top Layer w0.2: TP10.1 C5.2@82.5,53.3 ; R5.2 83.948,54.533 83.733,54.533 83.2,54 83.2,53.8 82.8,53.4 C5.2 82.6,53.4 C5.2@82.5,53.3 ; IC1.2 84.255,49.45 84.089,49.616 84.089,49.717 83.972,49.834 83.766,49.834 82.5,51.1 81.976,51.1 81.8,51.276 81.8,52.524 81.976,52.7 82.083,52.7 82.2,52.817 82.2,53 C5.2@82.5,53.3
"": C2.2 D1.A D2.+ L1.1 R14.2 R19.1 TP2.1 | length 92.5
  Top Layer w0.2: v1(69.3,16.1) 71.16,16.1 R14.2
  Top Layer w0.5: C2.2 93.1,30.889 93.393,30.596 93.401,30.596 93.595,30.401 D2.+ 95.251,30.05 TP2.1
  Bottom Layer w0.5: L1.1 66.85,65.292 66.85,38.568 68.634,36.784 75.771,36.784 80.055,32.5 D1.A 92.5,32.5 v1(93,33) v1(93,32) ; v1(69.3,16.1) 69.4,16.2 77.107,16.2 77.927,17.02 77.927,25.107 77.696,25.339 77.696,32.003 78.093,32.4 D1.A@80.055,32.4
pads on no net: R11.1

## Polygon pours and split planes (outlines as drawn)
"" on Top Layer "gg" (solid, pour order 24): 81.5,85 61,85 61,50.5 81.5,50.5
SW on Top Layer "gg" (solid, pour order 21): 72.549,27.579 67.021,27.579 67,27.6 67,30.4 68,31.4 68,34 71,34 71,32.1 72.5,30.6
PGND on Top Layer "gg" (solid, pour order 20): 71,36 71,31.1 78,31.1 78,36
VDD on Top Layer "gg" (solid, pour order 1): 62.749,29.179 64.064,29.179 64.364,28.879 65.539,28.879 65.539,30.769 65.549,30.779 62.749,30.779
HVIN on Top Layer "gg" (solid, pour order 2): 72.549,26.979 72.549,23.779 71.349,22.579 71.349,19.879 70.049,18.579 67.449,18.579 67.449,20.779 67.049,21.179 64.249,21.179 64.249,26.979
PGND on Top Layer "gg" (solid, pour order 5): 78,31.1 73.3,31.1 72.549,30.349 72.549,27.579 71.793,26.823 71.749,26.823 71.749,22.979 71.349,22.579 71.349,17 78,17
Udc on Top Layer "gg" (solid, pour order 16): 106.5,31 126,31 126,64 106.5,44.5
NetC6_2 on Top Layer "gg" (solid, pour order 15): 101.5,44.5 101.5,31 106.5,31 106.5,44.5
NetC6_2 on Top Layer "gg" (solid, pour order 14): 101.5,44.5 101.5,62 105,62 105,70 126,70 126,64 106.5,44.5
DRAIN on Top Layer "gg" (solid, pour order 13): 105,62 89,62 89,70 100.5,70 105,65.5
NetC4_1 on Top Layer "gg" (solid, pour order 12): 82,85 82,70 126,70 126,85
PGND on Top Layer "gg" (solid, remove dead copper, pour order 11): 80.2,36 80.2,44.5 88.6,44.5 90.7,46 93,46 93,44.5 101.5,44.5 101.5,28.2 80.2,28.2
GND on Top Layer "gg" (solid, pour order 10): 89.6,47.9 89.9,47.9 89.9,45.7 88.6,44.5 86.5,44.5 80.2,44.5 80.2,47.1 88.8,47.1
SOURCE on Top Layer "gg" (solid, pour order 8): 87.4,62.2 101.5,62.2 101.5,44.5 93,44.5 93,45.971 89.9,45.971 89.9,51.2 88.6,51.2 88.6,55.5 88.5,55.6 87.4,55.6
GND on Top Layer "gg" (solid, pour order 7): 86,46.2 86,47.6 85.3,48.3 85.3,48.945 85.261,48.984 85.277,49 87.9,49 88.2,49.3 89.6,49.3 89.6,47.9 87.9,46.2
15V on Top Layer "gg" (solid, pour order 6): 83.7,49 85.3,49 85.3,48.3 86,47.6 86,46.2 84.4,46.2 83.7,46.9
"" on Bottom Layer "gg" (solid, pour order 23): 81.5,85 61,85 61,50.5 81.5,50.5
Udc on Bottom Layer "gg" (solid, pour order 22): 103.6,48.3 103.7,48.4 121.8,48.4 123.9,46.3 123.9,40.8 118.8,35.7 118.8,14 103.6,14
PGND on Bottom Layer "gg" (solid, pour order 17): 81.5,40.5 126,40.5 126,85 81.5,85

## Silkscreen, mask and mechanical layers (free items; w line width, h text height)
Top Overlay:
  text "PFC UCC28056 v01-1 / Designer: Samo Smodis / Date: October 2023" at 62.125,79.506 h0.75
  text "HV+" at 109.801,22.5 h2
  text "HV-" at 119.434,22.5 h2
  text "AC" at 90.134,17 h2
Bottom Overlay:
  text "HV Set" at 67.466,43.741 h1.5
  text "HV+" at 117.166,22.6 h2
  text "HV-" at 125.366,22.6 h2
  text "AC" at 96.166,17 h2
  text "PFC UCC28056 v01-1 / Designer: Samo Smodis / Date: October 2023" at 112.375,14.506 h0.75
Board:
  the board outline again, w0.2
